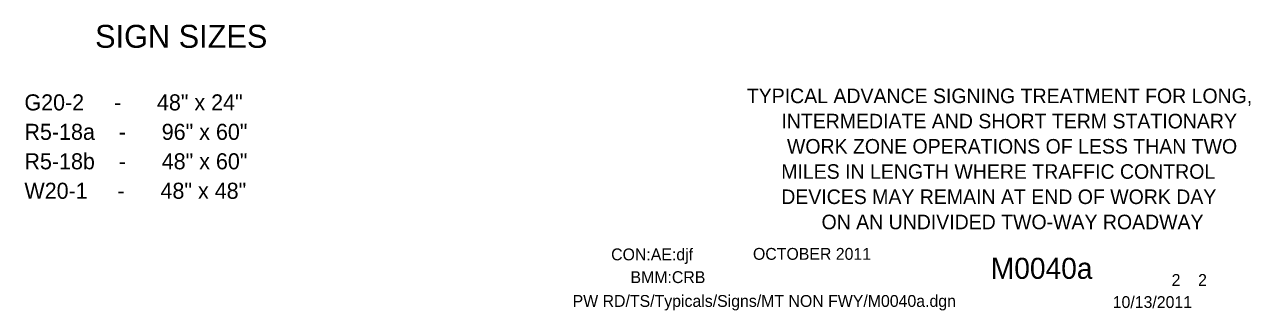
# Model space of a CAD drawing. Extents: x 19023 to 20747, y 5121 to 6119.
# Drawn here: x 20091 to 20732, y 5121 to 5271 of the extents above; entities that cross this region are included whole.
import ezdxf

# ---------------------------------------------------------------- set-up
doc = ezdxf.new("R2010")
doc.units = 0
for name, color, linetype in [('BORDER', 7, 'Continuous'), ('BORDER_SIGNAL_WO', 7, 'Continuous'), ('TYPICAL_TEXT_DIMEN_PR', 7, 'Continuous')]:
    doc.layers.add(name, color=color, linetype=linetype)

msp = doc.modelspace()

# ---------------------------------------------------------------- linework, layer by layer
at = {"layer": 'BORDER'}
msp.add_line((20596.417, 5194.208), (20596.417, 5194.208), dxfattribs=at)
msp.add_line((20596.417, 5194.208), (20596.417, 5194.208), dxfattribs=at)

# ---------------------------------------------------------------- texts
at = {"layer": 'BORDER_SIGNAL_WO'}
for s, height, p in [('TYPICAL ADVANCE SIGNING TREATMENT FOR LONG, ', 7.61553, (20468.805, 5229.463)), ('INTERMEDIATE AND SHORT TERM STATIONARY', 7.61553, (20486.866, 5216.276)), ('WORK ZONE OPERATIONS OF LESS THAN TWO', 7.61553, (20489.792, 5203.088)), ('MILES IN LENGTH WHERE TRAFFIC CONTROL ', 7.61553, (20486.804, 5189.899)), ('DEVICES MAY REMAIN AT END OF WORK DAY ', 7.61553, (20486.803, 5176.711)), ('ON AN UNDIVIDED TWO-WAY ROADWAY', 7.61553, (20507.866, 5163.523)), ('CON:AE:djf', 6.2, (20397.854, 5147.266)), ('    OCTOBER 2011    ', 6.2, (20462.801, 5147.547)), ('    M0040a   ', 11, (20580.029, 5137.588)), ('BMM:CRB   ', 6.2, (20407.977, 5135.382)), (' 2    2 ', 6.2, (20688.613, 5133.906)), ('PW RD/TS/Typicals/Signs/MT NON FWY/M0040a.dgn  ', 6.2, (20377.721, 5122.919)), ('10/13/2011    ', 6.19999, (20660.095, 5122.338))]:
    msp.add_text(s, height=height, dxfattribs=at).set_placement(p)
at = {"layer": 'TYPICAL_TEXT_DIMEN_PR'}
for s, height, p in [('SIGN SIZES', 12, (20128.036, 5258.4)), ('G20-2     -      48" x 24"', 8.4, (20091.089, 5225.659)), ('R5-18a    -      96" x 60"', 8.4, (20091.089, 5210.259)), ('R5-18b    -      48" x 60"', 8.4, (20091.089, 5194.859)), ('W20-1     -      48" x 48"', 8.4, (20091.089, 5179.459))]:
    msp.add_text(s, height=height, dxfattribs=at).set_placement(p)

doc.saveas('drawing.dxf')
